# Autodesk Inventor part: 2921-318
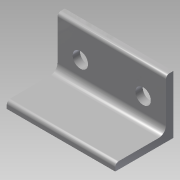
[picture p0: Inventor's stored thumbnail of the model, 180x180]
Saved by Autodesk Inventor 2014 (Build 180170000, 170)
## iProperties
Company: NHTSA/VRTC
Created: 2011-11
Part Number: 2921-318
Material: Steel
Document SubType Name: Modeling
Designer: Mike Vanvoorhis
Density: 7.85 g/cm^3
Project: CHILD SIDE IMPACT SLED
Description: BENCH LOWER ANCHOR MTG. ANGLE
Mass: 443.071 g
Surface Area: 202.345 cm^2
Volume: 56.4421 cm^3
Stock Number: L2" x 2" x 1/4" x 95.0mm (3 3/4")
Appearance: Steel
DESIGN DATE: 2012-11-05
Author: Dave Walker
Title: Bench Lower Anchor Mounting Angle
Subject: Child Side Impact Sled
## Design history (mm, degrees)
node "Sketch1"
node "2921-2101"
node "A_139"
node "A_140"
sketch "Sketch2"
  geometry: C1 r 6.79 at (20, 25.8) reference; C2 r 6.79 at (75, 25.8) reference; 1 further point
extrude "Extrusion1" join sketch "Sketch2" stored distance "d0" = 10; taper "d1" = 0 deg
sketch "Sketch3"
  geometry: L1 (0, 50.8)-(95, 50.8) reference; L2 (0, 50.8)-(0, 44.45) reference; 2 further points
  constraints: 1 horizontal alignment
  dimensions: "d2" = 25 distance from line of point (20, 25.8) L1; "d3" = 20 distance from line of point (20, 25.8) L2; "d4" = 55 distance of point (75, 25.8) point (20, 25.8)
hole "Hole1" sketch "Sketch3" at (20, 25.8), (75, 25.8) diameter "d5" = 13.49502; stored, may be unused: countersink angle "d9" = 90 deg, drill point angle "d11" = 118 deg; dims "d6" = 6, "d7" = 4, "d8" = 2, "d10" = 8
fillet "Fillet1" dims "d12" = 3.175
node "2921-210"
node "Base1"
